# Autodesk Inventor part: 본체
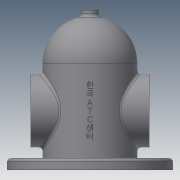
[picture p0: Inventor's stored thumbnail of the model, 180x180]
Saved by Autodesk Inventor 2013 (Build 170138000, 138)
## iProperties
Created: 2019-11
Part Number: 본체
Material: Generic
Document SubType Name: Modeling
Designer: 19
Density: 1 g/cm^3
Mass: 409.182 g
Surface Area: 886.455 cm^2
Volume: 409.182 cm^3
Author: 19
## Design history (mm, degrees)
sketch "스케치1"
  geometry: L1 (0, -50)-(0, 80); L2 (0, -50)-(40, -50); L3 (40, -50)-(40, 40); A1 r 40 centre (0, 40) between (40, 40) and (0, 80); 2 further points
  constraints: 6 end point, 2 perpendicular, 2 point on circle, 1 centre point, 1 midpoint, 1 vertical, 1 vertical alignment
  dimensions: "d0" = 130 distance of L1.start L1.end; "d2" = 50 distance of point (0, 0) L1.start; "d3" = 90 distance of L2.end L3.end; "d4" = 40 radius of A1; "d5" = 40 distance between parallel lines of L1 L3
revolve "회전1" sketch "스케치1" stored, may be unused: angle "d6" = 90 deg
feature "쉘1" dims "d7" = 10
sketch "스케치2"
  geometry: C1 r 40 at (0, 0) reference; C2 r 70 at (0, 0)
  constraints: 1 centre point, 1 coincident
  dimensions: "d8" = 140 diameter of C2
extrude "돌출1" join sketch "스케치2" distance "d9" = 10; taper "d10" = 0 deg
sketch "스케치3"
  geometry: L1 (0, 0)-(0, 55); L2 (0, 0)-(0, -55); C1 r 70 at (0, 0) reference; 2 further points
  constraints: 4 end point, 2 coincident, 1 collinear, 1 vertical
  dimensions: "d12" = 55 distance of L1.start L1.end; "d13" = 55 distance of L1.start L2.end
hole "구멍1" sketch "스케치3" at (0, 55), (0, -55) diameter "d14" = 9; stored, may be unused: countersink angle "d18" = 90 deg, drill point angle "d20" = 118 deg; dims "d15" = 6, "d16" = 4, "d17" = 2, "d19" = 8
node "작업 평면1"
sketch "스케치4"
  geometry: C1 r 31 at (0, 0); 1 further point
  constraints: 1 centre point, 1 coincident
  dimensions: "d22" = 62 diameter of C1
extrude "돌출2" join sketch "스케치4" stored distance "d23" = 10; taper "d24" = 0 deg
sketch "스케치5"
  geometry: C1 r 31 at (0, 0) reference; C2 r 20 at (0, 0)
  constraints: 1 centre point, 1 coincident
  dimensions: "d25" = 40 diameter of C2
extrude "돌출3" cut sketch "스케치5" distance "d26" = 15; taper "d27" = 0 deg
sketch "스케치6"
  geometry: C1 r 31 at (0, 0) reference; C2 r 20 at (0, 0)
  constraints: 1 centre point, 1 coincident
  dimensions: "d28" = 40 diameter of C2
extrude "돌출4" cut sketch "스케치6" distance "d29" = 15; taper "d30" = 0 deg
sketch "스케치7"
  geometry: C1 r 20 at (0, 0) reference; C2 r 16.5 at (0, 0)
  constraints: 1 centre point, 1 coincident
  dimensions: "d31" = 33 diameter of C2
extrude "돌출5" cut sketch "스케치7" stored distance "d32" = 15; taper "d33" = 0 deg
node "작업 평면2"
sketch "스케치8"
  geometry: C1 r 7.5 at (0, 0); 1 further point
  constraints: 1 centre point, 1 coincident
  dimensions: "d35" = 15 diameter of C1
extrude "돌출6" join sketch "스케치8" stored distance "d36" = 15; taper "d37" = 0 deg
sketch "스케치9"
  geometry: C1 r 7.5 at (0, 0) reference; 1 further point
  constraints: 1 coincident
hole "구멍2" sketch "스케치9" at (0, 0) diameter "d38" = 5.188; stored, may be unused: countersink angle "d42" = 90 deg, drill point angle "d44" = 118 deg; dims "d39" = 6, "d40" = 4, "d41" = 2, "d43" = 8
sketch "스케치10"
  geometry: L1 (0, 0)-(0, 26); C1 r 31 at (0, 0) reference; 1 further point
  constraints: 2 end point, 1 coincident, 1 vertical
  dimensions: "d45" = 26 distance of L1.start L1.end
hole "구멍3" sketch "스케치10" at (0, 26) diameter "d46" = 3.242; stored, may be unused: countersink angle "d50" = 90 deg, drill point angle "d52" = 118 deg; dims "d47" = 8, "d48" = 4, "d49" = 2, "d51" = 10
fillet "모깎기1" dims "d56" = 3
fillet "모깎기2" dims "d57" = 3
fillet "모깎기3" dims "d58" = 3
fillet "모깎기4" dims "d59" = 0.3
chamfer "모따기1" distance "d60" = 1; stored, may be unused: second distance "d61" = 2, angle "d62" = 45 deg
node "작업 평면3"
sketch "스케치11"
  geometry: L1 (70, -50)-(-70, -50) reference; 2 further points
  constraints: 1 coincident, 1 other
  dimensions: "d64" = 50 distance from line of L1 point (0, 0)
feature "엠보싱1" sketch "스케치11" dims "d12" = 55, "d13" = 55, "d65" = 0.5, "d66" = 0
node "솔리드1"
mirror "대칭1"
pattern_circular "원형 패턴1" dims angle "d54" = 360 deg
mirror "대칭2"
other parameters: "d34" = 85
